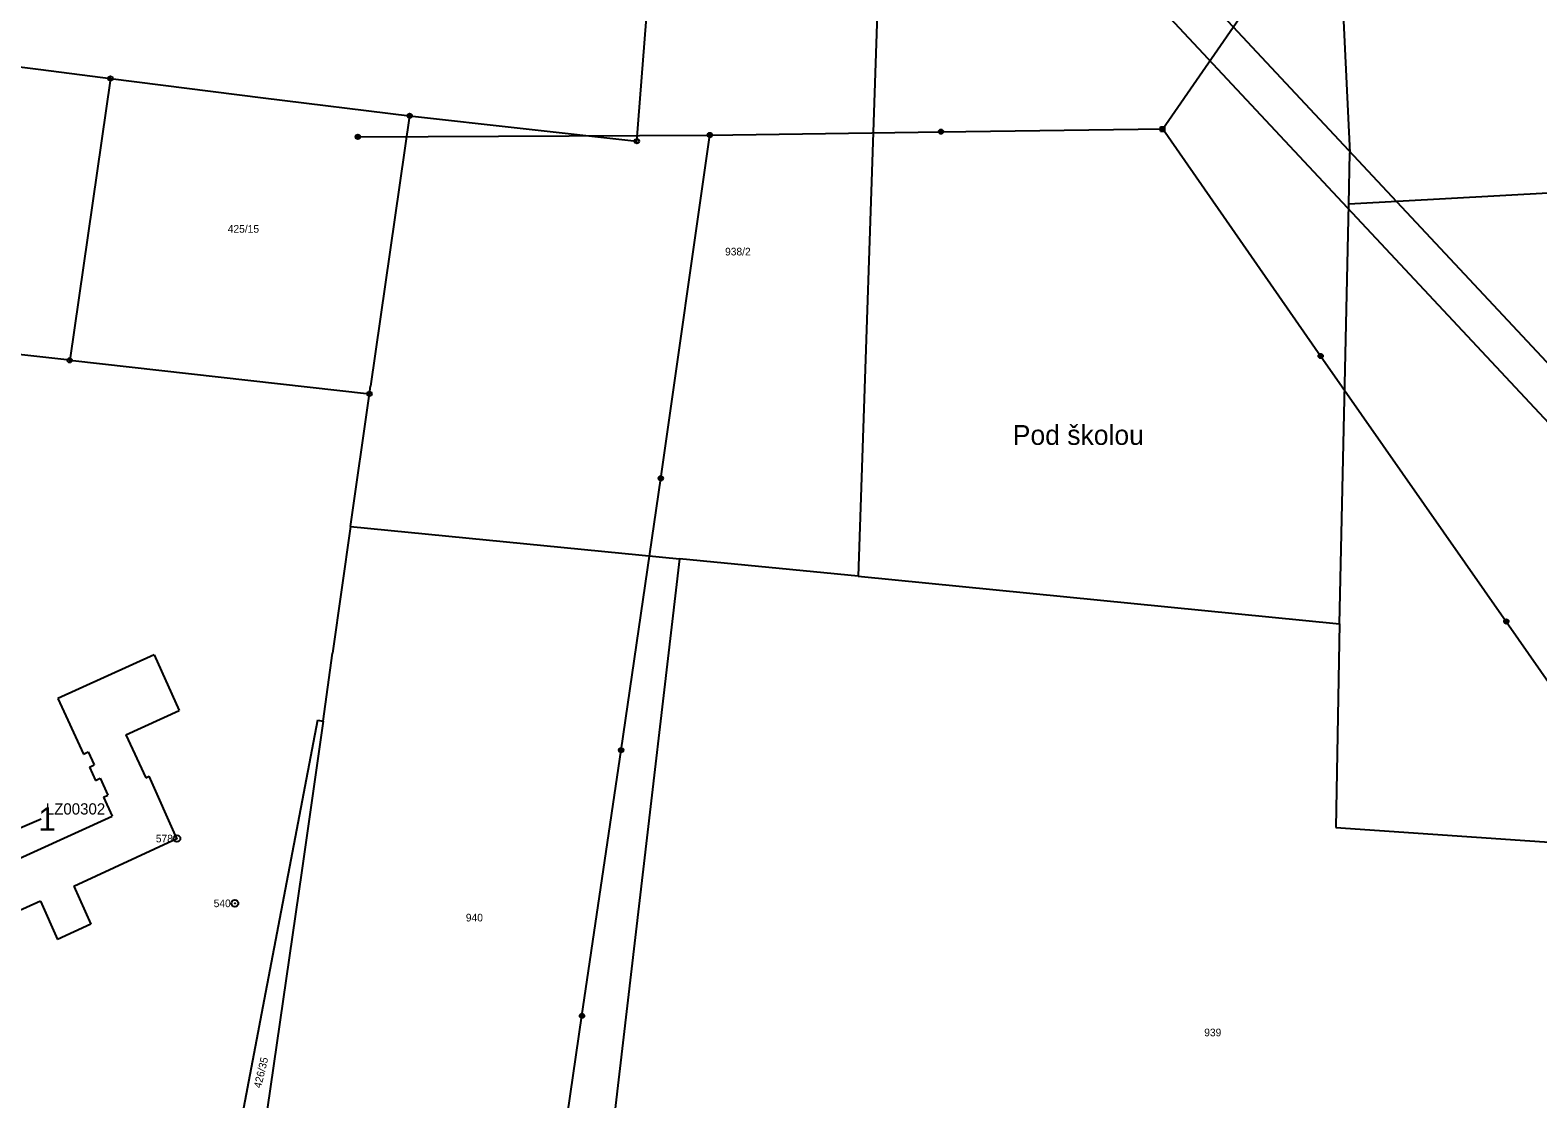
# Model space of a CAD drawing. Extents: x -738131 to -734179, y -1033447 to -1030078.
# Drawn here: x -735564.5 to -735229.5, y -1031919.1 to -1031681.6 of the extents above; entities that cross this region are included whole.
import ezdxf

# ---------------------------------------------------------------- set-up
doc = ezdxf.new("R2010")
doc.units = 0
for name, color, linetype in [('ftf_2010', 7, 'Continuous'), ('ftf_3010', 7, 'Continuous'), ('ftf_3010_ftf_3010_gtda_3015_gtda_3015_1', 7, 'Continuous'), ('Vrstva 1', 7, 'Continuous'), ('Vrstva 2', 7, 'Continuous'), ('Vrstva 6', 7, 'Continuous'), ('Vrstva 7', 7, 'Continuous'), ('Vrstva 8', 7, 'Continuous')]:
    doc.layers.add(name, color=color, linetype=linetype)

msp = doc.modelspace()

# ---------------------------------------------------------------- linework, layer by layer
at = {"layer": 'ftf_2010'}
msp.add_lwpolyline([(-735561.98, -1031856.88), (-735596.45, -1031871.66)], dxfattribs=at)
at = {"layer": 'Vrstva 1'}
for points in [[(-735480.16, -1031700.61), (-735429.68, -1031706.26), (-735419.14, -1031570.73)], [(-735276.42, -1031602.42), (-735271.28, -1031708.87)], [(-735376.16, -1031673.49), (-735380.53, -1031802.94)], [(-735613.46, -1031683.93), (-735562.1, -1031690.37)], [(-735562.1, -1031690.37), (-735546.63, -1031692.34)], [(-735546.63, -1031692.34), (-735555.68, -1031754.95)], [(-735546.63, -1031692.34), (-735512.69, -1031696.66)], [(-735512.69, -1031696.66), (-735480.16, -1031700.61)], [(-735480.16, -1031700.61), (-735488.83, -1031760.73)], [(-735271.54, -1031720.26), (-735271.28, -1031708.87)], [(-735160.2, -1031714.1), (-735271.54, -1031720.26)], [(-735273.63, -1031813.47), (-735271.54, -1031720.26)], [(-735555.68, -1031754.95), (-735607.17, -1031749.21)], [(-735555.68, -1031754.95), (-735489.06, -1031762.38)], [(-735489.06, -1031762.38), (-735488.83, -1031760.73)], [(-735493.27, -1031791.89), (-735489.06, -1031762.38)], [(-735493.27, -1031791.89), (-735497.27, -1031820.03)], [(-735493.27, -1031791.89), (-735420.23, -1031799.05)], [(-735420.23, -1031799.05), (-735439.89, -1031967.37)], [(-735380.53, -1031802.94), (-735420.23, -1031799.05)], [(-735380.53, -1031802.94), (-735273.63, -1031813.47)], [(-735273.63, -1031813.47), (-735274.44, -1031858.76)], [(-735536.94, -1031820.42), (-735558.29, -1031830.13)], [(-735536.94, -1031820.42), (-735531.36, -1031832.76)], [(-735499.4, -1031835.14), (-735497.27, -1031820.03)], [(-735558.29, -1031830.13), (-735552.62, -1031842.43)], [(-735543.19, -1031838.14), (-735531.36, -1031832.76)], [(-735500.63, -1031834.93), (-735512.46, -1031896.99)], [(-735500.63, -1031834.93), (-735499.4, -1031835.14)], [(-735543.19, -1031838.14), (-735538.77, -1031847.72)], [(-735499.4, -1031835.14), (-735504.08, -1031868.33)], [(-735552.62, -1031842.43), (-735551.59, -1031841.96)], [(-735551.59, -1031841.96), (-735550.25, -1031844.86)], [(-735551.28, -1031845.33), (-735550.25, -1031844.86)], [(-735551.28, -1031845.33), (-735549.91, -1031848.29)], [(-735549.91, -1031848.29), (-735548.88, -1031847.83)], [(-735548.88, -1031847.83), (-735547.17, -1031851.54)], [(-735538.77, -1031847.72), (-735538.03, -1031847.38)], [(-735531.85, -1031861.21), (-735538.03, -1031847.38)], [(-735548.19, -1031852.01), (-735547.17, -1031851.54)], [(-735548.19, -1031852.01), (-735546.24, -1031856.24)], [(-735598.49, -1031880.01), (-735546.24, -1031856.24)], [(-735554.76, -1031871.82), (-735531.85, -1031861.21)], [(-735274.44, -1031858.76), (-735157, -1031866.81)], [(-735504.08, -1031868.33), (-735511.82, -1031921.45)], [(-735554.76, -1031871.82), (-735550.97, -1031880.27)], [(-735562.18, -1031875.16), (-735602.86, -1031893.48)], [(-735562.18, -1031875.16), (-735558.39, -1031883.61)], [(-735550.97, -1031880.27), (-735558.39, -1031883.61)], [(-735512.46, -1031896.99), (-735522.25, -1031948.39)]]:
    msp.add_lwpolyline(points, dxfattribs=at)
at = {"layer": 'Vrstva 6'}
for p, q in [((-735313.38, -1031703.04), (-735312.38, -1031703.04)), ((-735313.38, -1031704.04), (-735313.38, -1031703.04)), ((-735313.38, -1031703.24), (-735312.38, -1031703.24)), ((-735313.38, -1031703.44), (-735312.38, -1031703.44)), ((-735313.38, -1031703.64), (-735312.38, -1031703.64)), ((-735313.38, -1031703.84), (-735312.38, -1031703.84)), ((-735313.38, -1031704.04), (-735312.38, -1031704.04)), ((-735313.18, -1031704.04), (-735313.18, -1031703.04)), ((-735312.98, -1031704.04), (-735312.98, -1031703.04)), ((-735312.78, -1031704.04), (-735312.78, -1031703.04)), ((-735312.58, -1031704.04), (-735312.58, -1031703.04)), ((-735312.38, -1031704.04), (-735312.38, -1031703.04))]:
    msp.add_line(p, q, dxfattribs=at)
for points in [[(-735312.88, -1031703.54), (-735285.05, -1031663.31)], [(-735304.82, -1031672.61), (-735085.11, -1031907.68)], [(-735311.38, -1031678.75), (-735091.67, -1031913.81)], [(-735413.49, -1031704.89), (-735362.12, -1031704.16)], [(-735362.12, -1031704.16), (-735312.88, -1031703.54)], [(-735312.88, -1031703.54), (-735277.79, -1031753.99)], [(-735491.67, -1031705.28), (-735413.49, -1031704.89)], [(-735424.36, -1031781.19), (-735413.49, -1031704.89)], [(-735277.79, -1031753.99), (-735236.55, -1031812.97)], [(-735433.19, -1031841.58), (-735424.36, -1031781.19)], [(-735236.55, -1031812.97), (-735194.12, -1031873.79)], [(-735441.88, -1031900.62), (-735433.19, -1031841.58)], [(-735450.23, -1031957.72), (-735441.88, -1031900.62)]]:
    msp.add_lwpolyline(points, dxfattribs=at)
for centre, radius in [((-735413.49, -1031704.89), 0.5), ((-735362.12, -1031704.16), 0.5), ((-735362.12, -1031704.16), 0.4), ((-735362.12, -1031704.16), 0.3), ((-735362.12, -1031704.16), 0.2), ((-735362.12, -1031704.16), 0.1), ((-735491.67, -1031705.28), 0.5), ((-735491.67, -1031705.28), 0.4), ((-735491.67, -1031705.28), 0.3), ((-735491.67, -1031705.28), 0.2), ((-735491.67, -1031705.28), 0.1), ((-735413.49, -1031704.89), 0.4), ((-735413.49, -1031704.89), 0.3), ((-735413.49, -1031704.89), 0.2), ((-735413.49, -1031704.89), 0.1), ((-735277.79, -1031753.99), 0.5), ((-735277.79, -1031753.99), 0.4), ((-735277.79, -1031753.99), 0.3), ((-735277.79, -1031753.99), 0.2), ((-735277.79, -1031753.99), 0.1), ((-735424.36, -1031781.19), 0.5), ((-735424.36, -1031781.19), 0.4), ((-735424.36, -1031781.19), 0.3), ((-735424.36, -1031781.19), 0.2), ((-735424.36, -1031781.19), 0.1), ((-735236.55, -1031812.97), 0.5), ((-735236.55, -1031812.97), 0.4), ((-735236.55, -1031812.97), 0.3), ((-735236.55, -1031812.97), 0.2), ((-735236.55, -1031812.97), 0.1), ((-735433.19, -1031841.58), 0.5), ((-735433.19, -1031841.58), 0.4), ((-735433.19, -1031841.58), 0.3), ((-735433.19, -1031841.58), 0.2), ((-735433.19, -1031841.58), 0.1), ((-735441.88, -1031900.62), 0.5), ((-735441.88, -1031900.62), 0.4), ((-735441.88, -1031900.62), 0.3), ((-735441.88, -1031900.62), 0.2), ((-735441.88, -1031900.62), 0.1)]:
    msp.add_circle(centre, radius, dxfattribs=at)
at = {"layer": 'Vrstva 8'}
for centre, radius in [((-735546.63, -1031692.34), 0.5), ((-735546.63, -1031692.34), 0.0303), ((-735480.16, -1031700.61), 0.5), ((-735480.16, -1031700.61), 0.0303), ((-735429.68, -1031706.26), 0.5), ((-735429.68, -1031706.26), 0.0303), ((-735555.68, -1031754.95), 0.5), ((-735555.68, -1031754.95), 0.0303), ((-735489.06, -1031762.38), 0.5), ((-735489.06, -1031762.38), 0.0303), ((-735531.85, -1031861.21), 0.75), ((-735531.85, -1031861.21), 0.03), ((-735518.97, -1031875.61), 0.75), ((-735518.97, -1031875.61), 0.03)]:
    msp.add_circle(centre, radius, dxfattribs=at)

# ---------------------------------------------------------------- texts
at = {"layer": 'ftf_3010'}
msp.add_text('1', height=5.2, dxfattribs=at).set_placement((-735562.63, -1031859.48))
at = {"layer": 'ftf_3010_ftf_3010_gtda_3015_gtda_3015_1'}
msp.add_text('LZ00302', height=2.5, dxfattribs=at).set_placement((-735560.98, -1031855.88))
at = {"layer": 'Vrstva 2'}
for s, p in [('425/15', (-735520.56, -1031726.6)), ('938/2', (-735410.09, -1031731.65)), ('940', (-735467.68, -1031879.63)), ('939', (-735303.65, -1031905.15))]:
    msp.add_text(s, height=1.7, dxfattribs=at).set_placement(p)
msp.add_text('426/35', height=1.7, rotation=76.4405, dxfattribs=at).set_placement((-735513.18, -1031916.79))
at = {"layer": 'Vrstva 7'}
msp.add_text('Pod školou', height=4.4, dxfattribs=at).set_placement((-735346.18, -1031773.74))
at = {"layer": 'Vrstva 8'}
for s, p in [('578', (-735536.54, -1031862.06)), ('540', (-735523.69, -1031876.46))]:
    msp.add_text(s, height=1.7, dxfattribs=at).set_placement(p)

doc.saveas('drawing.dxf')
